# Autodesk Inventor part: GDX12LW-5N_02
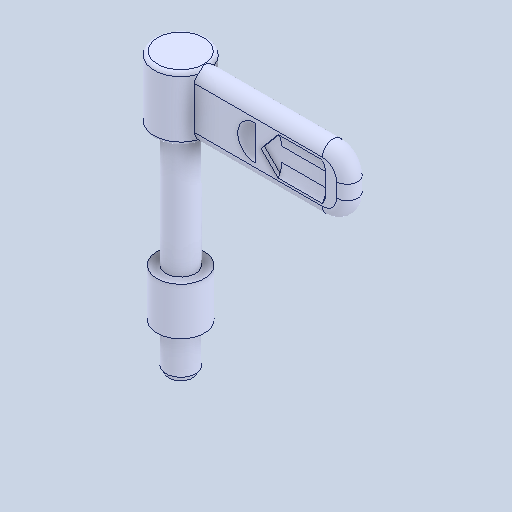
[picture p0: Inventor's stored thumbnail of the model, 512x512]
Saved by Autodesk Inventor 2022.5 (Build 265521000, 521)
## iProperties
Created: 2024-06
Part Number: GDX12LW-5N_02
Material: 一般
Document SubType Name: Modeling
Designer: ImaoCorp
Density: 1 g/cm^3
Appearance: 既定
Author: ImaoCorp
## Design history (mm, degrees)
feature "GDX12LW-5N_02"
node "ソリッド1"
